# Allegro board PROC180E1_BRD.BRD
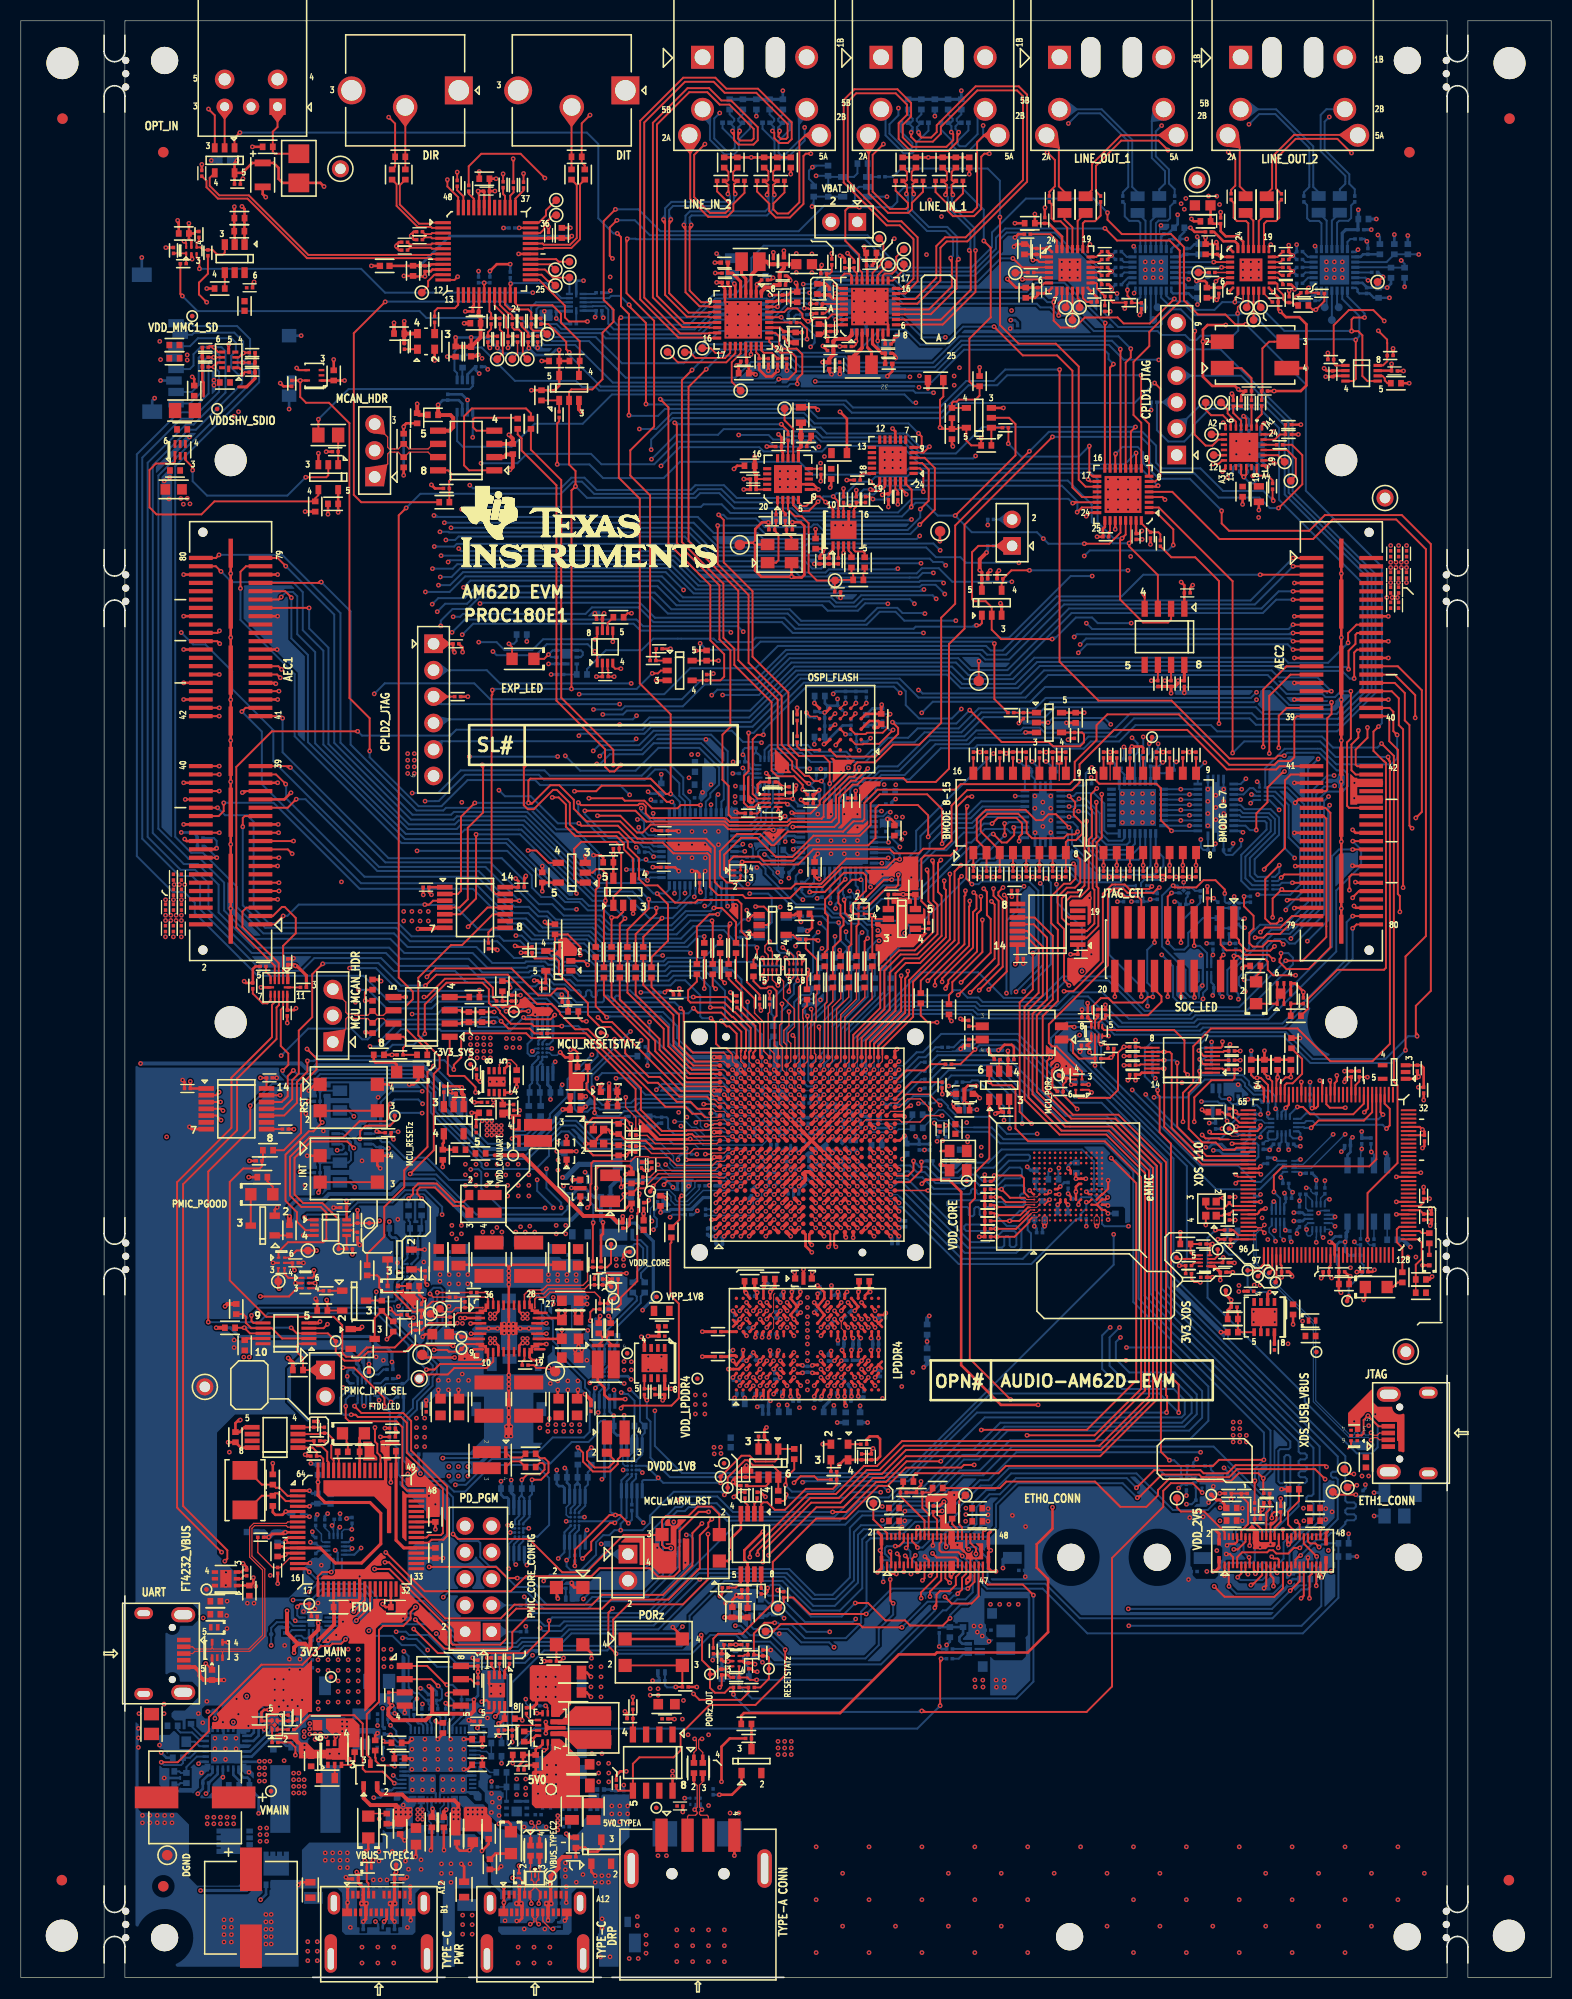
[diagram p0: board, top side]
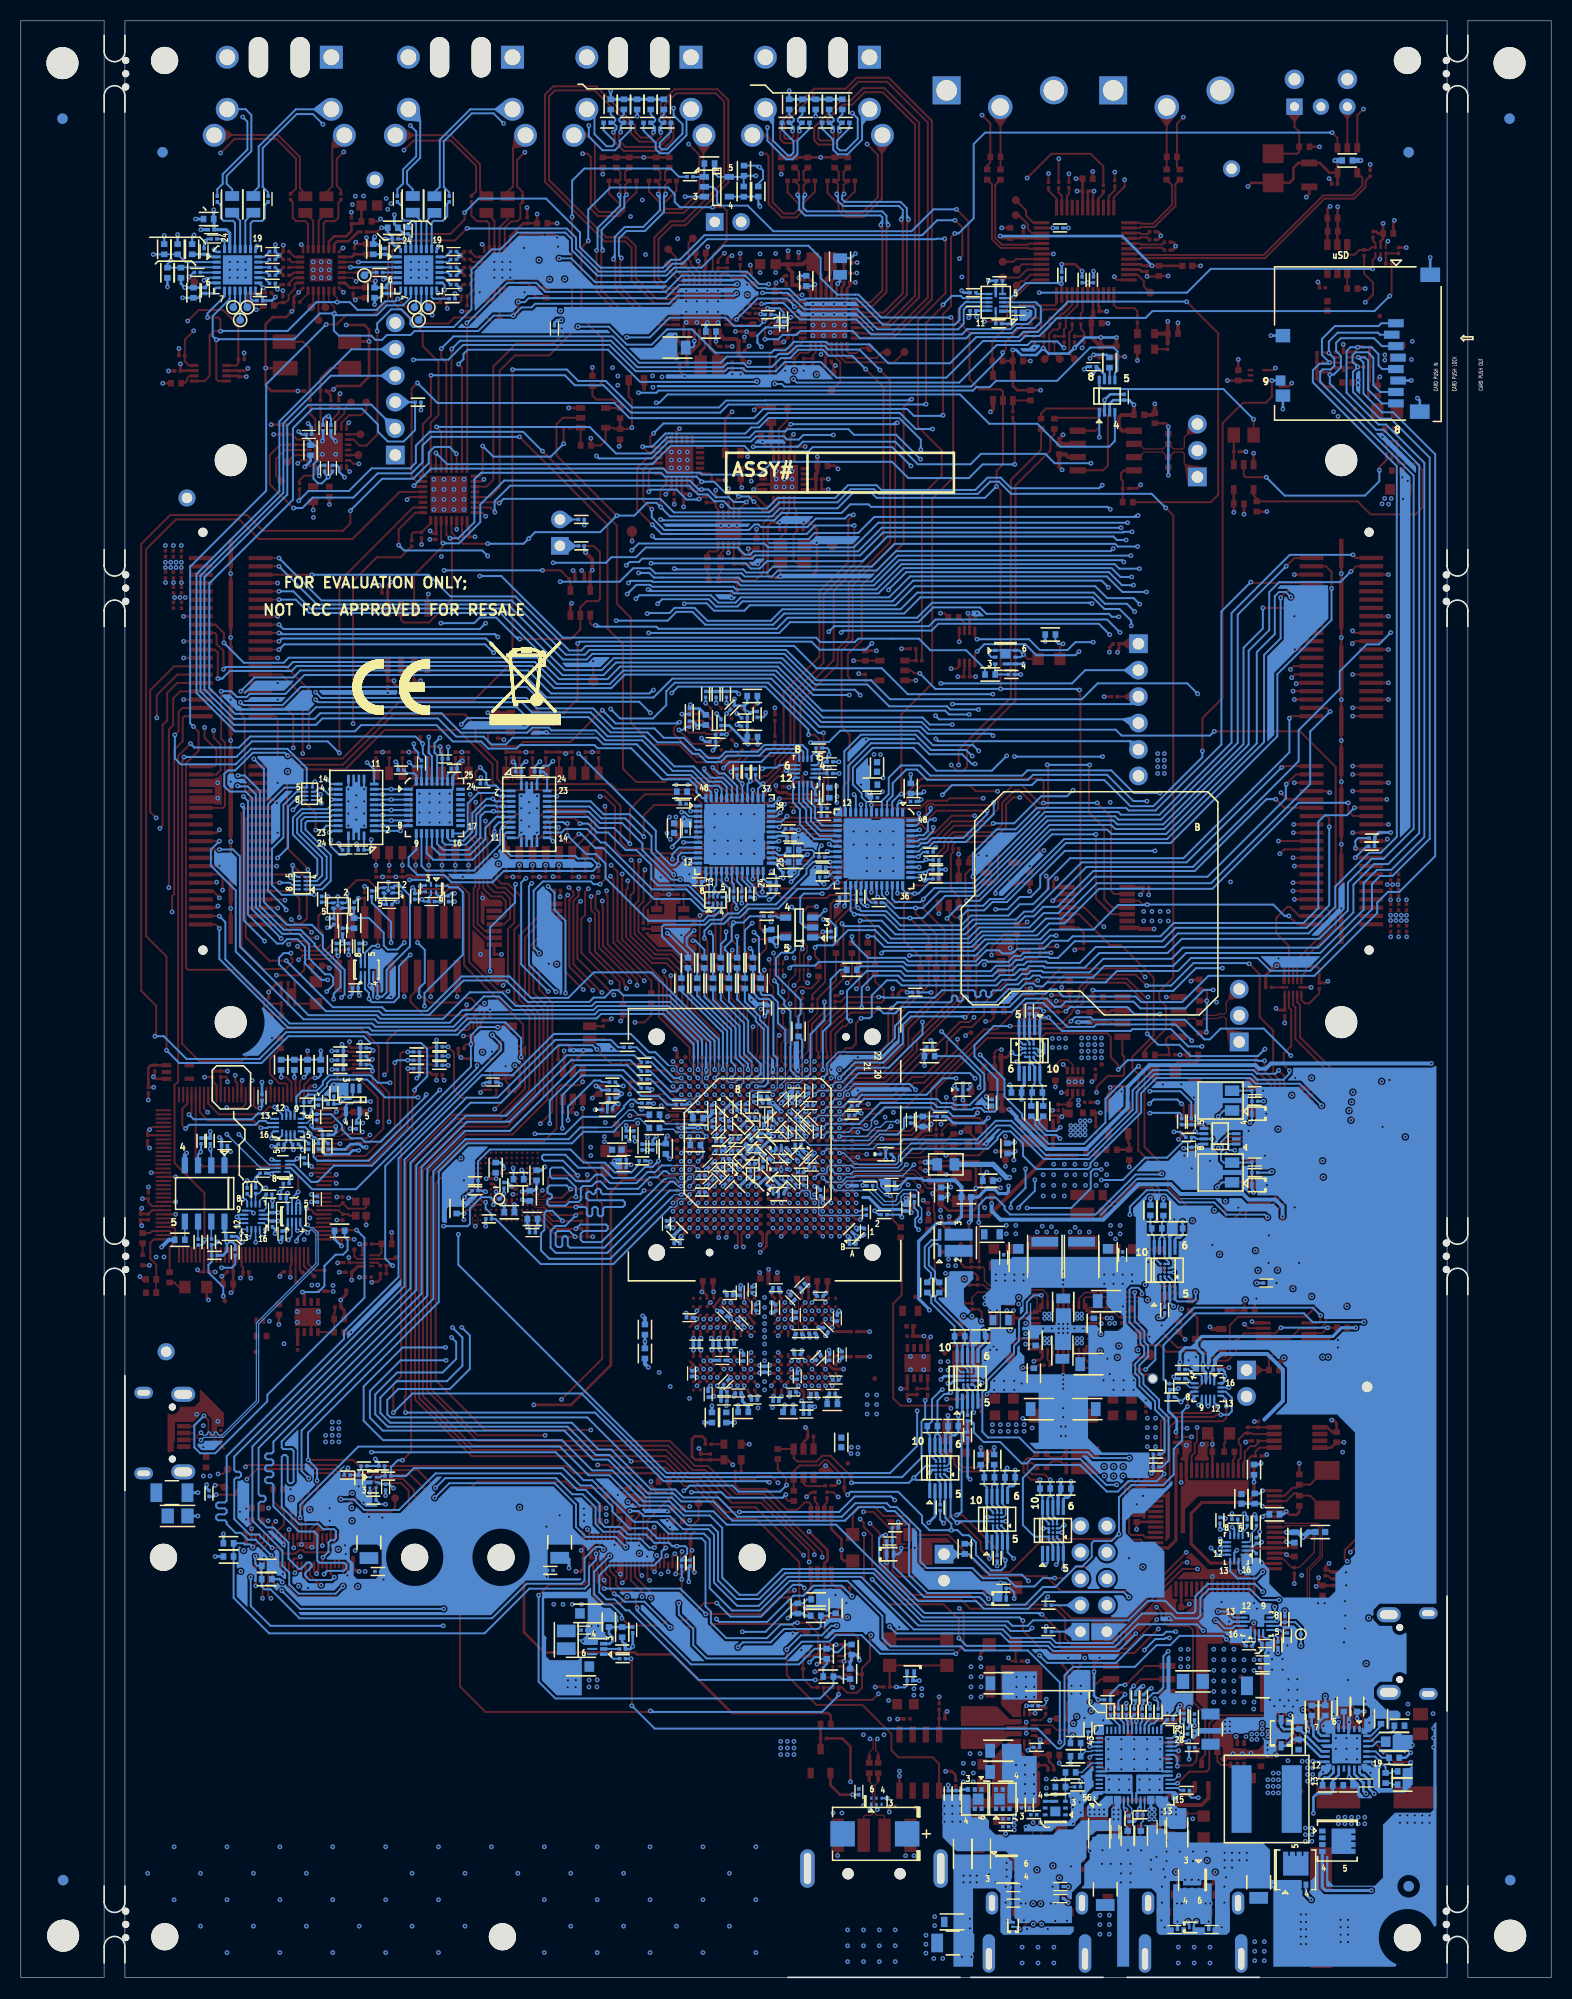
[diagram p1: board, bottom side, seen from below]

Outline 147 x 187.96 mm; copper layers: TOP, L02_GND01, L03_SIG01, L04_PWR1, L05_SIG02, L06_PWR2, L07_GND02, BOTTOM. Coordinates in mm from the lower left corner of the outline.
Outline path: 0,187.96 0,0 8,0 8,187.96 0,187.96 ; 10,187.96 10,0 137,0 137,187.96 10,187.96 ; 139,187.96 147,187.96 147,0 139,0 139,187.96

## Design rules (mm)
net group AUDIO_EXT_REFCLK0: nets AUDIO_EXT_REFCLK0 N27158712
net group AUDIO_EXT_REFCLK1: nets AUDIO_EXT_REFCLK1 AUDIO_EXT_REFCLK1__R
net group CLK_GEN_XI: nets CLK_GEN_XI N27177989
net group CLK_GEN_XO: nets CLK_GEN_XO N27177993
net group CPLD/EXP2_MCASP2_AFSR: nets CPLD/EXP2_MCASP2_AFSR CPLD_MCASP2_AFSR_R
net group CPLD/EXP2_MCASP2_AFSX: nets CPLD/EXP2_MCASP2_AFSX MCASP2_AFSX_R
net group CPLD/EXP2_MCASP2_AXR0: nets CPLD/EXP2_MCASP2_AXR0 MCASP2_AXR0_R
net group CPLD/EXP2_MCASP2_AXR1: nets CPLD/EXP2_MCASP2_AXR1 MCASP2_AXR1_R
net group CPLD/EXP2_MCASP2_AXR3: nets CPLD/EXP2_MCASP2_AXR3 MCASP2_AXR3_R
net group CPLD/EXP2_MCASP2_AXR4: nets CPLD/EXP2_MCASP2_AXR4 MCASP2_AXR4_R
net group CPLD/EXP2_MCASP2_AXR14: nets CPLD/EXP2_MCASP2_AXR14 MCASP2_AXR14_R
net group CPLD/EXP2_MCASP2_AXR15: nets CPLD/EXP2_MCASP2_AXR15 MCASP2_AXR15_R
net group CPLD_CDCE_CLKOUT_1: nets CPLD_CDCE_CLKOUT_1 N27176072
net group CPLD_CDCE_CLKOUT_2: nets CPLD_CDCE_CLKOUT_2 N27175754
net group CPLD_CLOCKIN: nets CPLD_CLOCKIN N27177966
net group CPLD_OBSCLK0: nets CPLD_OBSCLK0 CPLD_OBSCLK0_R
net group CPSW_RGMII1_TD0: nets CPSW_RGMII1_TD0 N27152136
net group CPSW_RGMII1_TD1: nets CPSW_RGMII1_TD1 N27152138
net group CPSW_RGMII1_TD2: nets CPSW_RGMII1_TD2 N27152140
net group CPSW_RGMII1_TD3: nets CPSW_RGMII1_TD3 N27152142
net group CPSW_RGMII1_TXC: nets CPSW_RGMII1_TXC CPSW_RGMII_TXC_R
net group CPSW_RGMII2_TD0: nets CPSW_RGMII2_TD0 N27152150
net group CPSW_RGMII2_TD1: nets CPSW_RGMII2_TD1 N27152152
net group CPSW_RGMII2_TD2: nets CPSW_RGMII2_TD2 N27152154
net group CPSW_RGMII2_TD3: nets CPSW_RGMII2_TD3 N27152156
net group CPSW_RGMII2_TXC: nets CPSW_RGMII2_TXC CPSW_RGMII2_TXC_R
net group DAC_LAT_CTRL: nets DAC_LAT_CTRL N27178331
net group DIX_MCLK: nets DIX_MCLK N26517285
net group DIX_OP_IN: nets DIX_OP_IN_N DIX_OP_IN_P
net group DIX_RX1: nets DIX_RX1_N DIX_RX1_P
net group DIX_RX2: nets DIX_RX2_N DIX_RX2_P
net group DIX_RX3: nets DIX_RX3_N DIX_RX3_P
net group DIX_TX: nets DIX_TX_N DIX_TX_P
net group EXP1_GPIO0_37: nets EXP1_GPIO0_37 EXP1_GPIO0_37_R
net group EXP2_MCASP2_AXR5: nets EXP2_MCASP2_AXR5 EXP2_MCASP2_AXR5_R
net group EXP2_MCASP2_AXR6: nets EXP2_MCASP2_AXR6 EXP2_MCASP2_AXR6_R
net group EXP2_MCASP2_AXR7: nets EXP2_MCASP2_AXR7 EXP2_MCASP2_AXR7_R
net group EXP2_MCASP2_AXR8: nets EXP2_MCASP2_AXR8 EXP2_MCASP2_AXR8_R
net group EXP2_MCASP2_AXR9: nets EXP2_MCASP2_AXR9 EXP2_MCASP2_AXR9_R
net group EXP2_MCASP2_AXR10: nets EXP2_MCASP2_AXR10 EXP2_MCASP2_AXR10_R
net group EXP2_MCASP2_AXR11: nets EXP2_MCASP2_AXR11 EXP2_MCASP2_AXR11_R
net group EXP2_MCASP2_AXR12: nets EXP2_MCASP2_AXR12 EXP2_MCASP2_AXR12_R
net group EXP2_MCASP2_AXR13: nets EXP2_MCASP2_AXR13 EXP2_MCASP2_AXR13_R
net group MCAN0: nets MCAN0_CAN_H MCAN0_CAN_L
net group MCAN1: nets MCAN1_CAN_H MCAN1_CAN_L
net group MMC1_CLK: nets MMC1_CLK MMC1_CLK_R
net group OSPI0_CSN0: nets OSPI0_CSN0 OSPI_CS
net group OSPI_CLK: nets OSPI_CLK SOC_OSPI_CLK
net group OSPI_DQS: nets OSPI_DQS OSPI_DQS_SOC
net group PCM1_IN1: nets PCM1_IN1N PCM1_IN1P
net group PCM1_IN2: nets PCM1_IN2N PCM1_IN2P
net group PCM1_IN3: nets PCM1_IN3N PCM1_IN3P
net group PCM1_IN4: nets PCM1_IN4N PCM1_IN4P
net group PCM2_IN1: nets PCM2_IN1N PCM2_IN1P
net group PCM2_IN2: nets PCM2_IN2N PCM2_IN2P
net group PCM2_IN3: nets PCM2_IN3N PCM2_IN3P
net group PCM2_IN4: nets PCM2_IN4N PCM2_IN4P
net group SEC_REF_N: nets N27175817 SEC_REF_N
net group SEC_REF_P: nets N27175821 SEC_REF_P
net group SOC_MMC0_CLK: nets MMC0_CLK SOC_MMC0_CLK
net group SOC_OSPI_DQ0: nets OSPI_DQ0 SOC_OSPI_DQ0
net group SOC_OSPI_DQ1: nets OSPI_DQ1 SOC_OSPI_DQ1
net group SOC_OSPI_DQ2: nets OSPI_DQ2 SOC_OSPI_DQ2
net group SOC_OSPI_DQ3: nets OSPI_DQ3 SOC_OSPI_DQ3
net group SOC_OSPI_DQ4: nets OSPI_DQ4 SOC_OSPI_DQ4
net group SOC_OSPI_DQ5: nets OSPI_DQ5 SOC_OSPI_DQ5
net group SOC_OSPI_DQ6: nets OSPI_DQ6 SOC_OSPI_DQ6
net group SOC_OSPI_DQ7: nets OSPI_DQ7 SOC_OSPI_DQ7
net group SOC_USB0: nets SOC_USB0_DM SOC_USB0_DP
net group SOC_USB1_DM: nets SOC_USB1_DM USB_TYPEACONN_DM
net group SOC_USB1_DP: nets SOC_USB1_DP USB_TYPEACONN_DP
net group TAD5212_1_DIN: nets TAD5212_1_DIN TAD5212_1_DIN_R
net group TAD5212_2_DIN: nets TAD5212_2_DIN TAD5212_2_DIN_R
net group TAD5212_3_DIN: nets TAD5212_3_DIN TAD5212_3_DIN_R
net group TAD5212_4_DIN: nets TAD5212_4_DIN TAD5212_4_DIN_R
net group TAD5212_MCASP2_ACLKX: nets N26567066 TAD5212_MCASP2_ACLKX
net group USBC_CONN2: nets USBC_CONN2_DM USBC_CONN2_DP
net group WKUP_LFOSCO_XO: nets N21761024 WKUP_LFOSCO_XO
net group XDS_USB: nets XDS_USB_DM XDS_USB_DP
net group EMMC: nets SOC_MMC0_DAT0
net group JTAG: nets N27154979 SOC_TCK SOC_TDI SOC_TDO SOC_TMS SOC_TRST#
net group MCU_SPI0: nets MCU_SPI0_CLK MCU_SPI0_D0 MCU_SPI0_D1
net group MMC0_SD-CARD: nets MMC1_SDCD
net group PWR: nets DIX_3V3_SYS VCC1V1_N VCC1V8_CLKBUF VCC1V8_SYS_N VCC_5V0_FB VCC_CORE_N

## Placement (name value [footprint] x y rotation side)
ACC*  -  [unnamed#4]  75.56 79.99 90 top
C1  0.1uF  [CAP0402_0-75]  23.71 175.85 180 top
C2  0.1uF  [CAP0402_0-75]  73.96 174.35 270 top
C3  0.1uF  [CAP0402_0-75]  91.1 174.35 270 top
C4  0.1uF  [CAP0201_0-5]  17.39 173.31 90 top
C5  0.1uF  [CAP0402_0-75]  52.9 173.19 90 top
C6  0.1uF  [CAP0402_0-75]  54.17 173.19 90 top
C7  0.1uF  [CAP0402_0-75]  35.66 173.19 90 top
C8  0.1uF  [CAP0402_0-75]  36.93 173.19 90 top
C9  10uF  [CAPCT0805H_1]  23.23 173.16 270 top
C10  10uF  [CAP0402_0-75]  44.52 172.79 180 top
C11  2.2uF  [CAP0201_0-75]  67.22 172.59 0 top
C12  2.2uF  [CAP0201_0-75]  69.17 172.59 180 top
C13  2.2uF  [CAP0201_0-75]  71.06 172.59 0 top
C14  2.2uF  [CAP0201_0-75]  73.01 172.59 180 top
C15  2.2uF  [CAP0201_0-75]  84.37 172.59 0 top
C16  2.2uF  [CAP0201_0-75]  86.32 172.59 180 top
C17  2.2uF  [CAP0201_0-75]  88.21 172.59 0 top
C18  2.2uF  [CAP0201_0-75]  90.16 172.59 180 top
C19  0.1uF  [CAP0201_0-5]  44.73 171.6 180 top
C20  1uF  [CAP0201_0-5]  116.26 171.07 270 top
C21  1uF  [CAP0201_0-5]  121.08 171.06 270 top
C22  1uF  [CAP0201_0-5]  98.79 170.85 270 top
C23  1uF  [CAP0201_0-5]  103.72 170.85 270 top
C24  47uF  [CAP0805_1-5]  100.25 170.3 270 top
C25  47uF  [CAP0805_1-5]  102.28 170.3 270 top
C26  47uF  [CAP0805_1-5]  117.65 170.3 270 top
C27  47uF  [CAP0805_1-5]  119.68 170.3 270 top
C28  0.1uF  [CAP0402_0-75]  21 169 180 top
C29  0.1uF  [CAP0201_0-5]  98.36 168.78 90 top
C30  0.1uF  [CAP0201_0-5]  115.25 168.75 90 top
C31  10uF  [CAP0402_0-75]  113.79 168.7 180 top
C32  10uF  [CAP0402_0-75]  96.92 168.51 180 top
C33  4.7uF  [CAP0402_0-75]  20.99 167.75 0 top
C34  0.1uF  [CAP0201_0-5]  38.3 167.7 180 top
C35  1uF  [CAP0201_0-5]  114.07 167.68 180 top
C36  10uF  [CAP0402_0-75]  51.97 167.58 90 top
C37  0.1uF  [CAP0402_0-75]  15.66 167.53 180 top
C38  1uF  [CAP0201_0-5]  96.68 167.46 180 top
C39  0.1uF  [CAP0201_0-5]  50.69 167.36 90 top
C40  0.1uF  [CAP0201_0-5]  38.3 166.93 180 top
C41  0.1uF  [CAP0201_0-5]  36.87 166.7 180 top
C42  10uF  [CAP0402_0-75]  96.4 166.02 90 top
C43  10uF  [CAP0402_0-75]  113.8 166.02 90 top
C44  0.1uF  [CAP0201_0-5]  36.87 165.93 180 top
C45  0.1uF  [CAP0201_0-5]  97.55 165.81 90 top
C46  0.1uF  [CAP0201_0-5]  114.95 165.81 90 top
C47  0.1uF  [CAP0201_0-5]  104.11 165.79 0 top
C48  0.1uF  [CAP0201_0-5]  121.51 165.79 0 top
C49  0.1uF  [CAP0402_0-75]  81.7 165.66 0 top
C50  0.1uF  [CAP0201_0-5]  104.11 165.03 0 top
C51  0.1uF  [CAP0201_0-5]  121.51 165.03 0 top
C52  2.2uF  [CAP0201_0-75]  73.3 164.91 90 top
C53  0.1uF  [CAP0201_0-5]  72.28 164.85 270 top
C54  2.2uF  [CAP0201_0-75]  67.58 164.73 180 top
C55  1uF  [CAP0201_0-5]  81.51 164.48 0 top
C56  0.1uF  [CAP0201_0-5]  104.11 164.27 0 top
C57  0.1uF  [CAP0201_0-5]  121.51 164.27 0 top
C58  0.1uF  [CAP0201_0-5]  38.82 164.15 270 top
C59  10uF  [CAP0402_0-75]  37.68 163.94 270 top
C60  0.1uF  [CAP0201_0-5]  67.64 163.72 0 top
C61  0.1uF  [CAP0201_0-5]  104.11 163.51 0 top
C62  0.1uF  [CAP0201_0-5]  121.51 163.51 0 top
C63  1uF  [CAP0201_0-5]  73.17 163.46 0 top
C64  0.1uF  [CAP0201_0-5]  71.44 163.07 0 top
C65  1uF  [CAP0201_0-5]  67.64 162.83 180 top
C66  1uF  [CAP0201_0-5]  104.11 162.62 0 top
C67  1uF  [CAP0201_0-5]  121.51 162.62 0 top
C68  0.1uF  [CAP0201_0-5]  73.17 162.57 0 top
C69  1uF  [CAP0201_0-5]  21.98 162.31 0 top
C70  220pF  [CAP0402_0-75]  19.1 162.24 180 top
C71  10uF  [CAP0402_0-75]  76.52 162.2 90 top
C72  0.1uF  [CAP0201_0-5]  97.68 162.05 270 top
C73  0.1uF  [CAP0201_0-5]  115.08 162.05 270 top
C74  0.1uF  [CAP0201_0-5]  77.66 161.91 90 top
C75  10uF  [CAP0402_0-75]  96.53 161.84 270 top
C76  10uF  [CAP0402_0-75]  113.92 161.84 270 top
C77  10uF  [CAP0402_0-75]  74.58 161.42 90 top
C78  0.1uF  [CAP0201_0-5]  73.17 161.34 90 top
C79  0.1uF  [CAP0201_0-5]  43.7 160.05 180 top
C80  10uF  [CAP0402_0-75]  43.67 158.9 180 top
C81  0.1uF  [CAP0201_0-5]  77.77 158.4 270 top
C82  10uF  [CAP0402_0-75]  76.66 158.34 270 top
C83  4.7uF  [CAP0402_0-75]  36.34 157.91 180 top
C84  0.1uF  [CAP0201_0-5]  73.28 157.83 270 top
C85  10uF  [CAP0402_0-75]  74.43 157.54 270 top
C86  0.1uF  [CAP0201_0-5]  77.77 157.17 180 top
C87  1uF  [CAP0201_0-5]  83.31 156.91 0 top
C88  2.2uF  [CAP0402_0-75]  14.75 156.81 0 top
C89  0.1uF  [CAP0201_0-5]  79.5 156.67 180 top
C90  1uF  [CAP0201_0-5]  77.77 156.28 180 top
C91  10uF  [CAP0402_0-75]  41.76 156.18 270 top
C92  0.1uF  [CAP0201_0-5]  83.31 156.02 180 top
C93  0.1uF  [CAP0402_0-75]  14.76 155.55 0 top
C94  0.1uF  [CAP0402_0-75]  51.23 155.28 180 top
C95  1uF  [CAP0201_0-5]  69.44 155.26 180 top
C96  2.2uF  [CAP0201_0-75]  83.37 155.01 0 top
C97  0.1uF  [CAP0201_0-5]  78.66 154.89 90 top
C98  2.2uF  [CAP0201_0-75]  77.65 154.83 270 top
C99  0.1uF  [CAP0201_0-5]  131.95 154.32 0 top
C100  0.1uF  [CAP0402_0-75]  69.44 154.12 180 top
C101  0.1uF  [CAP0201_0-5]  126.03 154.05 90 top
C102  0.1uF  [CAP0402_0-75]  30.05 153.89 270 top
C103  0.1uF  [CAP0402_0-75]  19.6 153.22 0 top
C104  12pF  [CAP0201_0-5]  117.94 152.4 0 top
C105  12pF  [CAP0201_0-5]  119.47 152.39 0 top
C106  0.1uF  [CAP0402_0-75]  39.59 150.11 0 top
C107  4700pF  [CAP0402_0-75]  38.07 149.78 90 top
C108  2.2uF  [CAP0402_0-75]  15.49 148.71 0 top
C109  0.1uF  [CAP0402_0-75]  89.44 148.26 270 top
C110  10uF  [CAP0402_0-75]  75.42 148.08 0 top
C111  0.1uF  [CAP0201_0-5]  75.21 147.06 0 top
C112  0.1uF  [CAP0201_0-5]  72.79 147.06 180 top
C113  0.1uF  [CAP0402_0-75]  47.26 146.82 270 top
C114  10uF  [CAP0402_0-75]  70 145.21 180 top
C115  0.1uF  [CAP0402_0-75]  14.81 144.76 180 top
C116  0.1uF  [CAP0201_0-5]  76.86 144.66 270 top
C117  10uF  [CAP0402_0-75]  77.84 144.43 270 top
C118  0.1uF  [CAP0201_0-5]  70.35 143.94 180 top
C119  10uF  [CAP0603_1]  14.68 142.94 180 top
C120  0.1uF  [CAP0201_0-5]  70.35 142.94 180 top
C121  10uF  [CAP0402_0-75]  117.36 142.72 270 top
C122  0.01uF  [CAP0201_0-5]  83.34 142.23 90 top
C123  0.1uF  [CAP0402_0-75]  29.99 141.56 180 top
C124  12pF  [CAP0201_0-5]  72.14 139.07 180 top
C125  12pF  [CAP0201_0-5]  73.83 139.07 180 top
C126  0.01uF  [CAP0201_0-5]  107.13 138.42 90 top
C127  10uF  [CAP0402_0-75]  76.34 137.74 90 top
C128  0.1uF  [CAP0201_0-5]  131.58 136.77 90 top
C129  0.1uF  [CAP0201_0-5]  132.35 136.77 90 top
C130  1uF  [CAP0201_0-5]  133.11 136.77 90 top
C131  0.1uF  [CAP0201_0-5]  76.74 136.07 270 top
C132  0.1uF  [CAP0201_0-5]  77.63 136.07 270 top
C133  0.1uF  [CAP0201_0-5]  131.58 134.71 270 top
C134  1uF  [CAP0201_0-5]  132.34 134.71 270 top
C135  1uF  [CAP0201_0-5]  133.1 134.71 270 top
C136  0.1uF  [CAP0201_0-5]  92.59 134.34 0 top
C137  0.1uF  [CAP0201_0-5]  131.58 133.27 90 top
C138  1uF  [CAP0201_0-5]  132.34 133.27 90 top
C139  0.01uF  [CAP0201_0-5]  78.46 133.1 0 top
C140  0.1uF  [CAP0201_0-5]  112.04 133 0 top
C141  0.1uF  [CAP0201_0-5]  131.58 131.82 270 top
C142  1uF  [CAP0201_0-5]  132.34 131.82 270 top
C143  0.1uF  [CAP0201_0-5]  55.58 130.47 180 top
C144  0.1uF  [CAP0201_0-5]  56.14 124.96 180 top
C145  0.1uF  [CAP0201_0-5]  41.79 128.11 0 top
C146  0.1uF  [CAP0402_0-75]  65.87 126.98 90 top
C147  0.1uF  [CAP0201_0-5]  111.76 124.29 270 top
C148  0.1uF  [CAP0402_0-75]  101.32 121 270 top
C149  4.7uF  [CAP0402_0-75]  82.65 120.89 90 top
C150  0.1uF  [CAP0201_0-5]  72.19 114.83 180 top
C151  0.1uF  [CAP0201_0-5]  73.81 114.09 270 top
C152  0.1uF  [CAP0201_0-5]  79.42 113.01 270 top
C153  0.1uF  [CAP0201_0-5]  80.2 113.01 270 top
C154  0.1uF  [CAP0201_0-5]  75.84 112.77 180 top
C155  10uF  [CAP0402_0-75]  83.91 110.17 90 top
C156  0.1uF  [CAP0201_0-5]  61.82 110.15 0 top
C157  0.1uF  [CAP0402_0-75]  56.43 107.11 180 top
C158  10uF  [CAP0402_0-75]  76.25 106.68 90 top
C159  0.1uF  [CAP0201_0-5]  61.76 106.64 0 top
C160  1uF  [CAP0201_0-5]  14.66 105.69 90 top
C161  0.1uF  [CAP0201_0-5]  15.42 105.69 90 top
C162  0.1uF  [CAP0402_0-75]  50.09 105.66 90 top
C163  0.1uF  [CAP0201_0-5]  65.19 105.44 90 top
C164  0.1uF  [CAP0201_0-5]  38.92 104.73 180 top
C165  0.1uF  [CAP0201_0-5]  48.07 104.73 180 top
C166  0.1uF  [CAP0402_0-75]  85.93 104.51 90 top
C167  1uF  [CAP0201_0-5]  14.66 104.24 270 top
C168  0.1uF  [CAP0201_0-5]  15.42 104.24 270 top
C169  0.1uF  [CAP0201_0-5]  113.98 103.95 90 top
C170  1uF  [CAP0201_0-5]  13.9 102.81 90 top
C171  1uF  [CAP0201_0-5]  14.66 102.81 90 top
C172  0.1uF  [CAP0201_0-5]  15.42 102.81 90 top
C173  0.1uF  [CAP0402_0-75]  75.27 102.17 0 top
C174  1uF  [CAP0201_0-5]  13.89 100.75 270 top
C175  0.1uF  [CAP0201_0-5]  14.65 100.75 270 top
C176  0.1uF  [CAP0201_0-5]  15.42 100.75 270 top
C177  0.1uF  [CAP0201_0-5]  101.81 98.28 0 top
C178  0.1uF  [CAP0201_0-5]  96.01 97.88 0 top
C179  0.1uF  [CAP0201_0-5]  25.64 97.56 90 top
C180  4700pF  [CAP0402_0-75]  33.79 95.37 90 top
C181  0.1uF  [CAP0201_0-5]  50.42 95.27 90 top
C182  100pF  [CAP0201_0-5]  52.29 93.68 180 top
C183  0.1uF  [CAP0201_0-5]  25.59 92.64 270 top
C184  0.1uF  [CAP0402_0-75]  43.04 92.25 90 top
C185  0.1uF  [CAP0402_0-75]  44.31 92.25 90 top
C186  0.1uF  [CAP0201_0-5]  102.21 92.2 0 top
C187  0.1uF  [CAP0201_0-5]  102.15 89.55 0 top
C188  100pF  [CAP0201_0-5]  53.19 88.38 180 top
C189  0.01uF  [CAP0201_0-5]  95.11 88.16 180 top
C190  0.01uF  [CAP0201_0-5]  134.14 87.34 270 top
C191  0.1uF  [CAP0201_0-5]  43.78 86.96 90 top
C192  0.1uF  [CAP0201_0-5]  106.79 86.73 180 top
C193  220pF  [CAP0402_0-75]  47.63 86.66 270 top
C194  0.1uF  [CAP0201_0-5]  23.88 86.41 0 top
C195  0.1uF  [CAP0201_0-5]  16 85.39 180 top
C196  10uF  [EMIFIL_NFM18C_0603_1-4]  56.51 85.07 0 top
C197  1uF  [CAP0201_0-5]  42.08 84.92 180 top
C198  10uF  [EMIFIL_NFM18C_0603_1-4]  90.64 84.88 0 top
C199  1uF  [CAP0201_0-5]  44.54 84.06 0 top
C200  10uF  [CAP0402_1]  56.83 83.7 180 top
C201  10uF  [CAP0402_1]  53.24 83.36 0 top
C202  10uF  [CAP0402_1]  90.64 83.3 0 top
C203  0.1uF  [CAP0201_0-5]  116.07 83.17 270 top
C204  10uF  [CAP0402_0-75]  44.5 83.05 180 top
C205  18pF  [CAP0402_0-75]  57.42 81.5 90 top
C206  1uF  [CAP0201_0-5]  88.3 81.5 90 top
C207  1uF  [CAP0201_0-5]  43.74 81.44 90 top
C208  0.01uF  [CAP0201_0-5]  134.82 80.62 270 top
C209  18pF  [CAP0402_0-75]  57.42 79.46 90 top
C210  10uF  [EMIFIL_NFM18C_0603_1-4]  52.42 79.36 90 top
C211  4.7uF  [CAP0201_0-5]  59.62 78.03 270 top
C212  1uF  [CAP0201_0-5]  60.61 78.03 270 top
C213  18pF  [CAP0402_0-75]  58.66 76.76 270 top
C214  10uF  [EMIFIL_NFM18C_0603_1-4]  53.74 75.82 90 top
C215  0.1uF  [CAP0201_0-5]  134.75 75.08 270 top
C216  18pF  [CAP0402_0-75]  58.66 74.84 90 top
C217  12pF  [CAP0201_0-5]  116.08 74.68 270 top
C218  10uF  [CAP0402_1]  61.45 74.59 90 top
C219  1uF  [CAP0201_0-5]  59.82 74.14 90 top
C220  0.1uF  [CAP0201_0-5]  31.01 73.94 0 top
C221  0.01uF  [CAP0201_0-5]  134.75 73.05 270 top
C222  1uF  [CAP0201_0-5]  135.51 73.05 270 top
C223  12pF  [CAP0201_0-5]  116.08 73.03 90 top
C224  1uF  [CAP0201_0-5]  57.82 72.25 270 top
C225  0.1uF  [CAP0201_0-5]  115.92 70.9 0 top
C226  22uF  [CAP0603_1]  40.14 69.17 270 top
C227  47uF  [CAP0805_1-5]  42.04 69.17 270 top
C228  47uF  [CAP0805_1-5]  51.7 69.17 270 top
C229  22uF  [CAP0603_1]  53.53 69.17 270 top
C230  0.1uF  [CAP0201_0-5]  26.37 68.64 180 top
C231  0.1uF  [CAP0201_0-5]  121.39 67.78 180 top
C232  0.01uF  [CAP0201_0-5]  125.37 67.78 180 top
C233  1uF  [CAP0201_0-5]  126.88 67.78 0 top
C234  0.01uF  [CAP0201_0-5]  129.12 67.78 180 top
C235  0.1uF  [CAP0201_0-5]  115.49 67.74 180 top
C236  0.1uF  [CAP0201_0-5]  113.63 67.25 180 top
C237  10uF  [CAP0402_0-75]  71.94 67.08 180 top
C238  10uF  [CAP0402_0-75]  70.01 66.87 180 top
C239  10uF  [CAP0402_0-75]  81 66.87 0 top
C240  2.2uF  [CAP0402_0-75]  127.09 66.61 0 top
C241  1uF  [CAP0201_0-5]  118.15 65.91 180 top
C242  2.2uF  [CAP0603_1]  52.77 65 0 top
C243  15pF  [CAP0201_0-5]  116.55 64.39 0 top
C244  2.2uF  [CAP0402_0-75]  122.21 64.17 270 top
C245  100pF  [CAP0201_0-5]  38.47 63.16 270 top
C246  2.2uF  [CAP0603_1]  52.77 63.15 0 top
C247  2.2uF  [CAP0201_0-75]  61.58 62.54 0 top
C248  100pF  [CAP0201_0-5]  37.92 62.44 90 top
C249  2.2uF  [CAP0603_1]  40.34 61.79 180 top
C250  4.7uF  [CAP0402_0-75]  123.89 61.61 180 top
C251  0.1uF  [CAP0201_0-5]  61.58 61.6 0 top
C252  2.2uF  [CAP0603_1]  52.77 61.34 0 top
C253  0.1uF  [CAP0402_0-75]  21.5 60.72 90 top
C254  2.2uF  [CAP0603_1]  52.77 59.54 0 top
C255  1uF  [CAP0201_0-5]  61.84 56.26 270 top
C256  2.2uF  [CAP0603_1]  40.31 54.79 90 top
C257  22uF  [CAP0603_1]  42.09 54.79 90 top
C258  22uF  [CAP0603_1]  51.65 54.79 90 top
C259  2.2uF  [CAP0603_1]  53.43 54.79 90 top
C260  0.1uF  [CAP0201_0-5]  54.77 54.66 90 top
C261  0.1uF  [CAP0201_0-5]  38.93 54.61 90 top
C262  0.1uF  [CAP0402_0-75]  20.62 51.89 270 top
C263  4.7uF  [CAP0402_0-75]  35.53 50.55 180 top
C264  0.1uF  [CAP0402_0-75]  33.03 50.49 180 top
C265  1uF  [CAP0201_0-5]  81.7 50 90 top
C266  0.1uF  [CAP0201_0-5]  80.76 50 270 top
C267  0.1uF  [CAP0402_0-75]  129.2 49.48 270 top
C268  0.01uF  [CAP0201_0-5]  69.61 48.33 270 top
C269  18pF  [CAP0402_0-75]  24.2 47.82 90 top
C270  18pF  [CAP0402_0-75]  24.2 45.78 270 top
C271  10uF  [CAP0402_0-75]  124.31 45.09 0 top
C272  10uF  [CAP0402_0-75]  83.88 45.09 0 top
C273  10uF  [CAP0402_0-75]  116.31 45.09 0 top
C274  10uF  [CAP0402_0-75]  91.86 45.06 0 top
C275  0.1uF  [CAP0402_0-75]  39.82 44.24 270 top
C276  0.1uF  [CAP0402_0-75]  116.31 43.88 0 top
C277  0.1uF  [CAP0402_0-75]  124.32 43.87 0 top
C278  0.1uF  [CAP0402_0-75]  83.88 43.84 0 top
C279  0.1uF  [CAP0402_0-75]  91.88 43.8 0 top
C280  0.1uF  [CAP0402_0-75]  24.66 40.92 90 top
C281  0.1uF  [CAP0402_0-75]  39.82 40.76 90 top
C282  0.1uF  [CAP0201_0-5]  24.67 39.09 90 top
C283  0.01uF  [CAP0201_0-5]  21.71 38.86 270 top
C284  0.1uF  [CAP0201_0-5]  69.53 37.24 0 top
C285  2.2uF  [CAP0402_0-75]  21.95 37.15 270 top
C286  1uF  [CAP0201_0-5]  69.53 36.48 0 top
C287  10uF  [CAP0402_0-75]  18.69 36.13 180 top
C288  0.1uF  [CAP0402_0-75]  30.53 35.57 180 top
C289  0.1uF  [CAP0402_0-75]  36.03 35.57 180 top
C290  10uF  [CAP0402_0-75]  68.35 35.07 90 top
C291  0.1uF  [CAP0402_0-75]  18.69 34.89 180 top
C292  0.1uF  [CAP0201_0-5]  43.91 30.19 90 top
C293  0.1uF  [CAP0201_0-5]  69.9 29.92 270 top
C294  10uF  [CAP0805_1-5]  53.06 29.27 0 top
C295  0.1uF  [CAP0402_0-75]  18.37 29.05 270 top
C296  10uF  [CAP0603_1]  53.06 27.36 0 top
C297  10uF  [CAP0603_1]  62.02 26.24 0 top
C298  0.1uF  [CAP0402_0-75]  46.97 24.85 0 top
C299  0.1uF  [CAP0201_0-5]  61.88 24.83 0 top
C300  0.01uF  [CAP0201_0-5]  22.84 24.64 0 top
C301  0.01uF  [CAP0201_0-5]  43.85 24.6 180 top
C302  10uF  [CAP0603_1]  29.29 24.21 0 top
C303  4.7uF  [CAP0402_0-75]  40.54 23.95 270 top
C304  0.1uF  [CAP0402_0-75]  48.36 23.13 270 top
C305  220pF  [CAP0402_0-75]  43.84 22.88 180 top
C306  220pF  [CAP0402_0-75]  36.1 22.53 0 top
C307  220pF  [CAP0402_0-75]  34.04 22.28 90 top
C308  330pF  [CAP0402_0-75]  32.06 22.12 90 top
C309  4.7uF  [CAP0402_0-75]  36.37 21.03 0 top
C310  1uF  [CAP0402_0-75]  27.89 20.76 90 top
C311  10uF  [CAP0603_1]  53.84 20.46 0 top
C312  220pF  [CAP0402_0-75]  43.84 20.42 180 top
C313  120pF  [CAP0201_0-5]  48.05 19.92 180 top
C314  22uF  [CAP0805_1-5]  53.86 18.43 0 top
C315  100uF  [CAPAE_FCASE_10-5]  16.74 17.29 180 top
C316  0.1uF  [CAP0201_0-5]  63.32 16.46 0 top
C317  47uF  [CAP0805_1-5]  52.93 15.92 270 top
C318  47uF  [CAP0805_1-5]  55.01 15.91 270 top
C319  10uF  [CAP0402_0-75]  39.48 14.9 90 top
C320  10uF  [CAP0402_0-75]  40.63 14.9 90 top
C321  0.1uF  [CAP0402_0-75]  36.43 14.26 270 top
C322  10uF  [CAP0603_1]  43.42 13.78 270 top
C323  0.1uF  [CAP0402_0-75]  44.94 13.78 270 top
C324  10uF  [CAP0603_1]  37.96 13.54 270 top
C325  0.1uF  [CAP0402_0-75]  41.89 13.43 270 top
C326  0.01uF  [CAP0201_0-5]  36.17 9.46 0 top
C327  0.01uF  [CAP0201_0-5]  32.14 9.45 180 top
C328  100uF  [CAPAE_FCASE_10-5]  22.11 6.68 270 top
C329  0.1uF  [CAP0402_0-75]  87.8 179.93 270 bottom
C330  0.1uF  [CAP0402_0-75]  70.65 179.93 270 bottom
C331  2.2uF  [CAP0201_0-75]  90.68 178.17 180 bottom
C332  2.2uF  [CAP0201_0-75]  88.73 178.17 0 bottom
C333  2.2uF  [CAP0201_0-75]  86.84 178.17 180 bottom
C334  2.2uF  [CAP0201_0-75]  84.89 178.17 0 bottom
C335  2.2uF  [CAP0201_0-75]  73.54 178.17 180 bottom
C336  2.2uF  [CAP0201_0-75]  71.59 178.17 0 bottom
C337  2.2uF  [CAP0201_0-75]  69.7 178.17 180 bottom
C338  2.2uF  [CAP0201_0-75]  67.75 178.17 0 bottom
C339  0.1uF  [CAP0402_0-75]  19.59 174.54 180 bottom
C340  0.1uF  [CAP0402_0-75]  77.54 173.56 90 bottom
C341  1uF  [CAP0201_0-5]  128.13 170.85 270 bottom
C342  1uF  [CAP0201_0-5]  123.25 170.85 270 bottom
C343  1uF  [CAP0201_0-5]  110.83 170.85 270 bottom
C344  1uF  [CAP0201_0-5]  105.85 170.85 270 bottom
C345  47uF  [CAP0805_1-5]  126.7 170.33 270 bottom
C346  47uF  [CAP0805_1-5]  124.67 170.33 270 bottom
C347  47uF  [CAP0805_1-5]  109.35 170.33 270 bottom
C348  47uF  [CAP0805_1-5]  107.27 170.3 270 bottom
C349  10uF  [CAP0402_0-75]  128.96 168.92 0 bottom
C350  10uF  [CAP0402_0-75]  111.27 168.08 0 bottom
C351  0.1uF  [CAP0201_0-5]  128.72 167.89 0 bottom
C352  0.1uF  [CAP0201_0-5]  109.79 167.76 90 bottom
C353  1uF  [CAP0201_0-5]  128.44 167 0 bottom
C354  1uF  [CAP0201_0-5]  111.04 167 0 bottom
C355  10uF  [CAP0402_0-75]  130.55 166.02 90 bottom
C356  10uF  [CAP0402_0-75]  113.15 166.02 90 bottom
C357  0.1uF  [CAP0201_0-5]  129.39 165.81 90 bottom
C358  0.1uF  [CAP0201_0-5]  112 165.81 90 bottom
C359  0.1uF  [CAP0201_0-5]  122.83 165.79 180 bottom
C360  0.1uF  [CAP0201_0-5]  105.43 165.79 180 bottom
C361  0.1uF  [CAP0201_0-5]  122.83 165.03 180 bottom
C362  0.1uF  [CAP0201_0-5]  105.43 165.03 180 bottom
C363  1uF  [CAP0805_1-5]  68.31 164.36 90 bottom
C364  0.1uF  [CAP0201_0-5]  122.83 164.27 180 bottom
C365  0.1uF  [CAP0201_0-5]  105.43 164.27 180 bottom
C366  0.1uF  [CAP0201_0-5]  122.83 163.51 180 bottom
C367  0.1uF  [CAP0201_0-5]  105.43 163.51 180 bottom
C368  10uF  [CAP0402_0-75]  71.56 162.98 90 bottom
C369  1uF  [CAP0201_0-5]  122.83 162.74 180 bottom
C370  1uF  [CAP0201_0-5]  105.43 162.62 180 bottom
C371  0.1uF  [CAP0201_0-5]  129.27 162.05 270 bottom
C372  0.1uF  [CAP0201_0-5]  111.87 162.05 270 bottom
C373  10uF  [CAP0402_0-75]  130.42 161.84 270 bottom
C374  10uF  [CAP0402_0-75]  113.02 161.84 270 bottom
C375  0.1uF  [CAP0201_0-5]  55.53 160.11 0 bottom
C376  0.1uF  [CAP0201_0-5]  51.15 160.06 180 bottom
C377  0.1uF  [CAP0201_0-5]  95.75 158.4 270 bottom
C378  10uF  [CAP0402_0-75]  80.72 158.11 0 bottom
C379  1uF  [CAP0805_1-5]  83.93 156.57 0 bottom
C380  0.1uF  [CAP0201_0-5]  43.98 154.73 0 bottom
C381  0.1uF  [CAP0201_0-5]  41.01 151.8 90 bottom
C382  0.1uF  [CAP0201_0-5]  117.97 148.85 270 bottom
C383  0.1uF  [CAP0201_0-5]  117.21 148.85 270 bottom
C384  0.1uF  [CAP0201_0-5]  119.33 148.22 180 bottom
C385  10uF  [CAP0402_0-75]  119.17 146.71 270 bottom
C386  0.1uF  [CAP0201_0-5]  117.83 144.97 90 bottom
C387  0.1uF  [CAP0201_0-5]  117.07 144.97 90 bottom
C388  0.1uF  [CAP0402_0-75]  76.74 123.09 180 bottom
C389  0.1uF  [CAP0402_0-75]  81.2 120.8 270 bottom
C390  0.1uF  [CAP0402_0-75]  76.73 119.16 180 bottom
C391  0.1uF  [CAP0201_0-5]  106.23 117.05 0 bottom
C392  0.1uF  [CAP0201_0-5]  69.27 116.77 0 bottom
C393  0.1uF  [CAP0201_0-5]  108.51 116.62 270 bottom
C394  0.1uF  [CAP0201_0-5]  99.2 115.82 180 bottom
C395  0.1uF  [CAP0201_0-5]  97.36 115.82 0 bottom
C396  0.1uF  [CAP0201_0-5]  69.29 115.65 0 bottom
C397  10uF  [CAP0402_0-75]  65.21 114.58 0 bottom
C398  10uF  [CAP0402_0-75]  61.52 114.21 90 bottom
C399  10uF  [CAP0402_0-75]  83.49 113.91 0 bottom
C400  10uF  [CAP0402_0-75]  69.34 113.8 90 bottom
C401  0.1uF  [CAP0201_0-5]  65 113.32 0 bottom
C402  0.1uF  [CAP0201_0-5]  61.26 112.96 180 bottom
C403  0.1uF  [CAP0201_0-5]  83.37 112.72 0 bottom
C404  0.1uF  [CAP0201_0-5]  69.83 112.31 0 bottom
C405  0.1uF  [CAP0201_0-5]  69.83 111.54 0 bottom
C406  0.1uF  [CAP0201_0-5]  83.09 110.37 90 bottom
C407  0.1uF  [CAP0201_0-5]  73.13 109.54 180 bottom
C408  0.1uF  [CAP0201_0-5]  115.81 108.3 0 bottom
C409  0.1uF  [CAP0201_0-5]  114.31 108.3 180 bottom
C410  0.1uF  [CAP0201_0-5]  69.97 106.65 0 bottom
C411  0.1uF  [CAP0201_0-5]  73.52 106.14 180 bottom
C412  0.1uF  [CAP0201_0-5]  81.89 105.25 0 bottom
C413  0.1uF  [CAP0201_0-5]  68.07 103.76 0 bottom
C414  0.1uF  [CAP0201_0-5]  107.55 103.35 0 bottom
C415  0.01uF  [CAP0201_0-5]  111.63 103.08 0 bottom
C416  0.01uF  [CAP0201_0-5]  116.94 101.44 90 bottom
C417  8.2pF  [CAP0201_0-5]  116.08 100.51 270 bottom
C418  0.1uF  [CAP0402_0-75]  74.9 100.16 90 bottom
C419  0.1uF  [CAP0201_0-5]  114.51 99.04 270 bottom
C420  0.1uF  [CAP0201_0-5]  114.87 95.06 180 bottom
C421  0.1uF  [CAP0201_0-5]  101.66 86.01 180 bottom
C422  1.0uF  [EMIFIL_NFM15CC_0402_0-5]  56.51 85.28 180 bottom
C423  1uF  [CAP0201_0-5]  90.18 85.23 0 bottom
C424  0.1uF  [CAP0201_0-5]  71.31 85.19 270 bottom
C425  0.1uF  [CAP0201_0-5]  28.47 85.18 0 bottom
C426  0.1uF  [CAP0201_0-5]  72.66 85.05 0 bottom
C427  0.1uF  [CAP0402_0-75]  51.36 85.01 180 bottom
C428  0.1uF  [CAP0402_0-75]  49.36 85.01 0 bottom
C429  0.1uF  [CAP0201_0-5]  75.6 84.65 0 bottom
C430  0.1uF  [CAP0201_0-5]  123.84 84.53 270 bottom
C431  1uF  [CAP0201_0-5]  90.18 84.47 0 bottom
C432  1uF  [CAP0201_0-5]  76.61 84.39 90 bottom
C433  1uF  [CAP0201_0-5]  71.96 84.39 135 bottom
C434  1uF  [CAP0201_0-5]  73.62 84.35 135 bottom
C435  1uF  [CAP0201_0-5]  72.9 84.26 90 bottom
C436  1uF  [CAP0201_0-5]  53.69 84.04 270 bottom
C437  0.1uF  [CAP0201_0-5]  75.45 83.99 0 bottom
C438  0.1uF  [CAP0201_0-5]  71.16 83.74 180 bottom
C439  0.1uF  [CAP0201_0-5]  78.21 83.59 270 bottom
C440  0.1uF  [CAP0201_0-5]  77.41 83.59 90 bottom
C441  0.1uF  [CAP0201_0-5]  80.64 83.5 90 bottom
C442  1.0uF  [EMIFIL_NFM15CC_0402_0-5]  90.66 83.35 180 bottom
C443  1uF  [CAP0201_0-5]  71.86 82.89 315 bottom
C444  1uF  [CAP0201_0-5]  75.16 82.87 270 bottom
C445  1uF  [CAP0201_0-5]  72.79 82.77 225 bottom
C446  1uF  [CAP0201_0-5]  79.81 82.74 90 bottom
C447  0.1uF  [CAP0201_0-5]  76.76 82.64 0 bottom
C448  10uF  [CAP0402_1]  81.95 82.52 0 bottom
C449  22pF  [CAP0201_0-5]  61.55 82.34 90 bottom
C450  0.1uF  [CAP0201_0-5]  75.63 82.31 90 bottom
C451  0.1uF  [CAP0201_0-5]  80.61 81.99 90 bottom
C452  1uF  [CAP0201_0-5]  79.01 81.99 90 bottom
C453  0.1uF  [CAP0201_0-5]  71.16 81.99 225 bottom
C454  1uF  [CAP0201_0-5]  71.91 81.94 45 bottom
C455  0.1uF  [CAP0201_0-5]  114.77 81.79 90 bottom
C456  0.1uF  [CAP0201_0-5]  73.61 81.24 225 bottom
C457  1uF  [CAP0201_0-5]  70.5 81.22 90 bottom
C458  0.1uF  [CAP0201_0-5]  79.96 81.19 315 bottom
C459  0.1uF  [CAP0201_0-5]  76.76 81.19 315 bottom
C460  0.1uF  [CAP0201_0-5]  72.9 81.19 270 bottom
C461  0.1uF  [CAP0201_0-5]  71.96 81.19 225 bottom
C462  0.1uF  [CAP0201_0-5]  75.53 81.07 180 bottom
C463  4.7uF  [CAP0201_0-5]  88.85 81.04 90 bottom
C464  4.7uF  [CAP0201_0-5]  88.09 81.04 90 bottom
C465  0.1uF  [CAP0201_0-5]  74.36 80.79 0 bottom
C466  1uF  [CAP0201_0-5]  78.36 80.54 0 bottom
C467  0.1uF  [CAP0201_0-5]  79.96 80.29 0 bottom
C468  2.2uF  [CAP0201_0-75]  77.08 80.21 135 bottom
C469  0.1uF  [CAP0201_0-5]  121.99 80.04 180 bottom
C470  0.1uF  [CAP0201_0-5]  120.61 80.04 0 bottom
C471  0.1uF  [CAP0201_0-5]  72.32 80.01 0 bottom
C472  0.1uF  [CAP0201_0-5]  79.09 79.93 135 bottom
C473  0.1uF  [CAP0201_0-5]  127.44 79.9 0 bottom
C474  4.7uF  [CAP0201_0-5]  87.33 79.76 90 bottom
C475  1uF  [CAP0201_0-5]  86.29 79.76 90 bottom
C476  10uF  [CAP0402_1]  52.22 79.64 270 bottom
C477  1uF  [CAP0201_0-5]  76.56 79.59 180 bottom
C478  0.1uF  [CAP0201_0-5]  34.53 79.46 90 bottom
C479  0.1uF  [CAP0201_0-5]  79.96 79.44 0 bottom
C480  0.1uF  [CAP0201_0-5]  78.36 79.44 180 bottom
C481  1.0uF  [EMIFIL_NFM15CC_0402_0-5]  63.92 79.08 180 bottom
C482  1.0uF  [EMIFIL_NFM15CC_0402_0-5]  72.11 78.94 315 bottom
C483  1uF  [CAP0201_0-5]  75.32 78.86 45 bottom
C484  1uF  [CAP0201_0-5]  71.14 78.77 135 bottom
C485  0.1uF  [CAP0201_0-5]  73.51 78.74 45 bottom
C486  0.1uF  [CAP0201_0-5]  79.26 78.65 180 bottom
C487  1uF  [CAP0201_0-5]  89.12 78.57 0 bottom
C488  1uF  [CAP0201_0-5]  119.76 78.46 90 bottom
C489  0.1uF  [CAP0201_0-5]  28.47 78.32 0 bottom
C490  0.1uF  [CAP0201_0-5]  76.76 78.14 0 bottom
C491  0.1uF  [CAP0201_0-5]  75.7 78.12 90 bottom
C492  1uF  [CAP0201_0-5]  80.77 78 315 bottom
C493  1uF  [CAP0201_0-5]  78.29 77.93 45 bottom
C494  0.1uF  [CAP0201_0-5]  79.01 77.86 90 bottom
C495  0.1uF  [CAP0201_0-5]  79.86 77.84 0 bottom
C496  0.1uF  [CAP0201_0-5]  71.03 77.84 0 bottom
C497  4.7uF  [CAP0201_0-5]  89.12 77.81 0 bottom
C498  0.1uF  [CAP0402_0-75]  101.39 77.78 90 bottom
C499  0.1uF  [CAP0201_0-5]  72.09 77.34 180 bottom
C500  0.1uF  [CAP0201_0-5]  123.74 77.25 180 bottom
C501  0.1uF  [CAP0201_0-5]  76.91 77.19 270 bottom
C502  0.1uF  [CAP0201_0-5]  79.92 77.13 45 bottom
C503  0.1uF  [CAP0402_0-75]  97.46 77.05 90 bottom
C504  2.2uF  [CAP0402_0-75]  99.18 76.67 0 bottom
C505  10uF  [CAP0402_1]  54.1 76.52 0 bottom
C506  0.1uF  [CAP0201_0-5]  80.76 76.39 315 bottom
C507  1uF  [CAP0201_0-5]  79.16 76.39 315 bottom
C508  0.1uF  [CAP0201_0-5]  72.76 76.39 225 bottom
C509  1uF  [CAP0201_0-5]  71.81 76.39 270 bottom
C510  1uF  [CAP0201_0-5]  63.36 76.38 0 bottom
C511  0.1uF  [CAP0201_0-5]  121.5 76.27 180 bottom
C512  0.1uF  [CAP0201_0-5]  63.36 75.69 0 bottom
C513  1uF  [CAP0201_0-5]  70.19 75.35 270 bottom
C514  0.1uF  [CAP0402_0-75]  98.12 75.08 270 bottom
C515  0.1uF  [CAP0201_0-5]  121.78 74.84 180 bottom
C516  0.1uF  [CAP0201_0-5]  118.51 74.76 270 bottom
C517  0.1uF  [CAP0201_0-5]  61.99 73.91 90 bottom
C518  2.2uF  [CAP0402_0-75]  105.14 73.87 90 bottom
C519  0.1uF  [CAP0201_0-5]  122.82 73.74 270 bottom
C520  0.1uF  [CAP0402_0-75]  100.08 73.5 0 bottom
C521  0.1uF  [CAP0402_0-75]  97.86 72.86 180 bottom
C522  0.1uF  [CAP0201_0-5]  84.99 72.39 90 bottom
C523  0.1uF  [CAP0201_0-5]  122.82 72.37 90 bottom
C524  0.1uF  [CAP0402_0-75]  37.88 71.95 180 bottom
C525  0.1uF  [CAP0402_0-75]  35.89 71.95 0 bottom
C526  0.1uF  [CAP0201_0-5]  65.97 71.64 270 bottom
C527  1uF  [CAP0201_0-5]  97.86 71.54 180 bottom
C528  0.1uF  [CAP0201_0-5]  121.91 71.41 90 bottom
C529  0.1uF  [CAP0201_0-5]  127.04 71.17 0 bottom
C530  0.1uF  [CAP0201_0-5]  83.96 70.49 0 bottom
C531  0.1uF  [CAP0201_0-5]  67.11 70.44 180 bottom
C532  0.1uF  [CAP0201_0-5]  41.16 69.4 270 bottom
C533  100uF  [CAP1210_2-75]  48.64 69.26 270 bottom
C534  100uF  [CAP1210_2-75]  45.11 69.26 270 bottom
C535  2.2uF  [CAP0603_1]  51.18 69.18 270 bottom
C536  2.2uF  [CAP0603_1]  42.57 69.18 270 bottom
C537  0.1uF  [CAP0201_0-5]  52.59 69.13 270 bottom
C538  0.1uF  [CAP0201_0-5]  27.34 66.7 180 bottom
C539  0.1uF  [CAP0201_0-5]  71.95 66.47 135 bottom
C540  1000pF  [CAP0201_0-5]  74.47 66.25 180 bottom
C541  0.01uF  [CAP0201_0-5]  76.75 66.06 270 bottom
C542  0.1uF  [CAP0201_0-5]  77.9 65.79 270 bottom
C543  0.01uF  [CAP0201_0-5]  78.91 65.49 0 bottom
C544  1000pF  [CAP0201_0-5]  70.22 65.44 180 bottom
C545  0.01uF  [CAP0201_0-5]  72.84 65.3 45 bottom
C546  10uF  [CAP0805_1-5]  42.76 64.96 180 bottom
C547  10uF  [CAP0805_1-5]  46.87 64.41 270 bottom
C548  0.1uF  [CAP0201_0-5]  76.4 64.35 90 bottom
C549  0.1uF  [CAP0201_0-5]  74.49 64.33 90 bottom
C550  0.1uF  [CAP0201_0-5]  79.4 63.69 45 bottom
C551  0.1uF  [CAP0201_0-5]  72.51 63.63 90 bottom
C552  0.1uF  [CAP0201_0-5]  82.78 63.37 0 bottom
C553  0.1uF  [CAP0201_0-5]  68.57 63.31 90 bottom
C554  0.1uF  [CAP0201_0-5]  77.84 62.83 225 bottom
C555  0.47uF  [CAP0402_0-75]  43.93 62.82 270 bottom
C556  0.1uF  [CAP0201_0-5]  69.68 62.2 45 bottom
C557  0.1uF  [CAP0201_0-5]  70.99 61.86 0 bottom
C558  0.1uF  [CAP0201_0-5]  72.26 61.83 0 bottom
C559  0.1uF  [CAP0402_0-75]  56.81 61.57 180 bottom
C560  0.1uF  [CAP0402_0-75]  54.82 61.57 0 bottom
C561  4.7uF  [CAP0402_0-75]  49.53 61.2 90 bottom
C562  0.1uF  [CAP0201_0-5]  78.78 60.86 180 bottom
C563  0.1uF  [CAP0201_0-5]  82.11 60.82 0 bottom
C564  0.1uF  [CAP0201_0-5]  80.22 60.82 180 bottom
C565  10uF  [CAP0805_1-5]  46.95 60.21 90 bottom
C566  0.1uF  [CAP0201_0-5]  72.4 59.84 0 bottom
C567  0.1uF  [CAP0201_0-5]  68.1 59.83 90 bottom
C568  0.1uF  [CAP0201_0-5]  69.31 59.56 270 bottom
C569  0.1uF  [CAP0201_0-5]  77.57 59.49 270 bottom
C570  1000pF  [CAP0201_0-5]  70.37 59.49 315 bottom
C571  1000pF  [CAP0201_0-5]  79.62 59.27 0 bottom
C572  10uF  [CAP0805_1-5]  44.44 58.91 180 bottom
C573  0.1uF  [CAP0201_0-5]  75.56 58.42 90 bottom
C574  0.1uF  [CAP0201_0-5]  33.72 58.37 180 bottom
C575  0.1uF  [CAP0201_0-5]  32.2 58.37 0 bottom
C576  0.47uF  [CAP0402_0-75]  49.69 58.03 270 bottom
C577  0.1uF  [CAP0201_0-5]  82.57 58 270 bottom
C578  0.1uF  [CAP0201_0-5]  72.42 57.73 270 bottom
C579  0.1uF  [CAP0201_0-5]  68.73 57.38 180 bottom
C580  0.1uF  [CAP0201_0-5]  79.28 57.17 315 bottom
C581  1000pF  [CAP0201_0-5]  79.46 56.25 0 bottom
C582  0.1uF  [CAP0201_0-5]  72.82 56.22 180 bottom
C583  1000pF  [CAP0201_0-5]  78.08 56.14 0 bottom
C584  0.01uF  [CAP0201_0-5]  69.05 56.1 0 bottom
C585  0.1uF  [CAP0201_0-5]  70.84 56.09 0 bottom
C586  0.1uF  [CAP0201_0-5]  80.98 56.02 90 bottom
C587  0.01uF  [CAP0201_0-5]  76.53 55.47 180 bottom
C588  0.1uF  [CAP0201_0-5]  79.46 55.36 0 bottom
C589  0.1uF  [CAP0201_0-5]  74.46 55.35 180 bottom
C590  10uF  [CAP0402_0-75]  69.05 55.09 180 bottom
C591  0.1uF  [CAP0201_0-5]  71.54 54.88 180 bottom
C592  47uF  [CAP0805_1-5]  49.2 54.58 180 bottom
C593  47uF  [CAP0805_1-5]  44.54 54.58 0 bottom
C594  0.01uF  [CAP0201_0-5]  71.54 54.12 0 bottom
C595  10uF  [CAP0402_0-75]  80.62 53.79 270 bottom
C596  10uF  [CAP0402_0-75]  79.24 53.79 270 bottom
C597  0.1uF  [CAP0402_0-75]  59.44 52.96 180 bottom
C598  0.1uF  [CAP0402_0-75]  57.44 52.96 0 bottom
C599  0.1uF  [CAP0402_0-75]  28.54 48.77 270 bottom
C600  0.1uF  [CAP0402_0-75]  53.97 48.03 180 bottom
C601  0.1uF  [CAP0402_0-75]  51.97 48.03 0 bottom
C602  0.1uF  [CAP0201_0-5]  111.96 47.09 270 bottom
C603  0.1uF  [CAP0402_0-75]  48.61 46.95 180 bottom
C604  0.1uF  [CAP0402_0-75]  46.62 46.95 0 bottom
C605  1000pF  [CAP1206_1-75]  132.49 46.56 0 bottom
C606  0.1uF  [CAP0402_0-75]  28.48 46 270 bottom
C607  0.1uF  [CAP0402_0-75]  24.66 42.26 90 bottom
C608  0.1uF  [CAP0201_0-5]  28.33 41.96 270 bottom
C609  0.1uF  [CAP0201_0-5]  63.56 41.91 180 bottom
C610  1000pF  [CAP1206_1-75]  95.24 41.8 90 bottom
C611  1000pF  [CAP1206_1-75]  113.56 41.78 90 bottom
C612  0.1uF  [CAP0201_0-5]  28.33 40.44 90 bottom
C613  0.1uF  [CAP0201_0-5]  52.63 37.38 180 bottom
C614  22uF  [CAP0603_1]  92.49 34.96 180 bottom
C615  120pF  [CAP0201_0-5]  88.22 33.37 90 bottom
C616  0.1uF  [CAP0201_0-5]  92.91 33.35 180 bottom
C617  0.1uF  [CAP0201_0-5]  27.5 32.06 0 bottom
C618  0.1uF  [CAP0201_0-5]  29.03 31.84 180 bottom
C619  0.1uF  [CAP0201_0-5]  27.72 30.5 0 bottom
C620  4.7uF  [CAP0603_1]  93.2 29.85 0 bottom
C621  0.1uF  [CAP0201_0-5]  27.72 29.74 0 bottom
C622  0.1uF  [CAP0201_0-5]  61.59 28.5 0 bottom
C623  10uF  [CAP0805_1-5]  53.07 28.25 0 bottom
C624  47uF  [CAP1206_2]  27.72 28.01 180 bottom
C625  0.1uF  [CAP0402_0-75]  18.64 26.02 270 bottom
C626  0.22uF  [CAP0402_0-75]  16.35 24.85 90 bottom
C627  2.2uF  [CAP0402_0-75]  24.18 24.34 90 bottom
C628  0.12uF  [CAP0603_1]  15.09 22.64 180 bottom
C629  0.1uF  [CAP0402_0-75]  24.26 22.36 90 bottom
C630  22uF  [CAP0805_1-5]  53.09 21.76 0 bottom
C631  4.7uF  [CAP0402_0-75]  45.68 21.24 0 bottom
C632  330pF  [CAP0402_0-75]  14.26 19.78 180 bottom
C633  22uF  [CAP0805_1-5]  53.09 19.73 0 bottom
C634  33pF  [CAP0201_0-5]  17.76 18.67 0 bottom
C635  15000pF  [CAP0402_0-75]  14.26 18.51 180 bottom
C636  0.1uF  [CAP0402_0-75]  19.48 18.44 180 bottom
C637  0.1uF  [CAP0201_0-5]  66.5 17.82 270 bottom
C638  0.1uF  [CAP0201_0-5]  57.16 17.65 90 bottom
C639  0.1uF  [CAP0201_0-5]  50.88 16.56 270 bottom
C640  0.1uF  [CAP0201_0-5]  52.38 15.23 180 bottom
C641  0.01uF  [CAP0201_0-5]  37.48 14.42 270 bottom
C642  0.01uF  [CAP0201_0-5]  41.9 13.93 270 bottom
C643  4.7uF  [CAP0805_1-5]  35.93 13.93 270 bottom
C644  4.7uF  [CAP0805_1-5]  43.42 13.83 270 bottom
C645  150uF_10V  [CAPT7343D_3-25]  64.96 13.78 0 bottom
C646  10uF  [CAP0603_1]  54.74 11.87 270 bottom
C647  10uF  [CAP0603_1]  56.52 11.84 270 bottom
C648  1000pF  [CAP1206_1-75]  28.1 9.13 90 bottom
C649  0.01uF  [CAP0201_0-5]  47.16 8.72 180 bottom
C650  0.01uF  [CAP0201_0-5]  51.67 8.61 0 bottom
C651  1000pF  [CAP1206_1-75]  42.83 8.45 90 bottom
C652  0.01uF  [CAP0201_0-5]  47.15 7.56 180 bottom
C653  0.01uF  [CAP0201_0-5]  51.66 7.12 0 bottom
C654  0.01uF  [CAP0201_0-5]  36.17 4.59 0 bottom
C655  0.01uF  [CAP0201_0-5]  32.61 4.59 180 bottom
C656  1000pF  [CAP1206_1-75]  57.48 3.3 180 bottom
C657  1.0uF  [EMIFIL_NFM15CC_0402_0-5]  73.96 79.7 180 bottom
C658  1.0uF  [EMIFIL_NFM15CC_0402_0-5]  79.16 83.59 225 bottom
C659  1.0uF  [EMIFIL_NFM15CC_0402_0-5]  77.56 81.99 225 bottom
C660  1.0uF  [EMIFIL_NFM15CC_0402_0-5]  77.56 78.79 135 bottom
C661  1.0uF  [EMIFIL_NFM15CC_0402_0-5]  74.51 82.14 135 bottom
C662  1.0uF  [EMIFIL_NFM15CC_0402_0-5]  73.96 77.63 180 bottom
C663  1.0uF  [EMIFIL_NFM15CC_0402_0-5]  75.5 80.02 225 bottom
C664  10uF  [EMIFIL_NFM18C_0603_1-4]  75.18 67.14 0 top
C665  1.0uF  [EMIFIL_NFM15CC_0402_0-5]  75.72 76.53 45 bottom
C666  1.0uF  [EMIFIL_NFM15CC_0402_0-5]  74.21 75.25 180 bottom
C667  1.0uF  [EMIFIL_NFM15CC_0402_0-5]  74.36 76.39 135 bottom
C668  1.0uF  [EMIFIL_NFM15CC_0402_0-5]  77.56 76.39 225 bottom
C669  1.0uF  [EMIFIL_NFM15CC_0402_0-5]  67 71.43 135 bottom
C670  1.0uF  [EMIFIL_NFM15CC_0402_0-5]  83.96 71.59 225 bottom
D1  TPD1E10B06DPYR  [DIO_DFN0402_0-5]  124.03 63.09 0 top
D2  PLVA650A  [DIO_SOT23_123]  32.84 61.33 0 top
D3  TPD1E10B06DPYR  [DIO_DFN0402_0-5]  18.58 33.63 180 top
D4  BZX84C6V8LT1G  [SOT23-123_1-2]  70.18 20.77 90 top
D5  BAT54CWT1G  [DIO_SOT323-3_1-1]  33.58 19.48 90 top
D6  BZX84C6V8LT1G  [SOT23-123_1-2]  55.75 12.06 90 top
D7  TPD1E01B04DPLT  [DIO_DFN0201_0-4]  33.45 10.52 0 top
D8  TPD1E01B04DPLT  [DIO_DFN0201_0-4]  47.86 9.77 90 top
D9  ESD122DMXR  [X2SON3_ESD122DMX_30X40_0-4]  49.39 9.53 270 top
D10  TPD1E10B06DPYR  [DIO_DFN0402_0-5]  28.41 82.97 0 bottom
D11  TPD1E10B06DPYR  [DIO_DFN0402_0-5]  28.41 76.11 0 bottom
D12  TPD1E10B06DPYR  [DIO_DFN0402_0-5]  63.49 40.65 180 bottom
D13  TPD1E10B06DPYR  [DIO_DFN0402_0-5]  52.69 36.38 180 bottom
D14  TPD1E10B06DPYR  [DIO_DFN0402_0-5]  61.53 29.3 0 bottom
D15  XBS104S13R  [DIO_SOD323_1]  25.95 23.49 90 bottom
D16  TPD1E01B04DPLT  [DIO_DFN0201_0-4]  51.69 5.07 90 bottom
D17  TPD1E01B04DPLT  [DIO_DFN0201_0-4]  34.54 4.79 180 bottom
FL1  120E  [EMIFIL_BLM18P_0603_0-8]  113.53 170.22 0 top
FL2  120E  [EMIFIL_BLM18P_0603_0-8]  75.24 164.57 180 top
FL3  120E  [EMIFIL_BLM15A_0402_0-6]  34.95 164.42 0 top
FL4  120E  [EMIFIL_BLM15A_0402_0-6]  21.49 160.56 270 top
FL5  120E  [EMIFIL_BLM15A_0402_0-6]  43.26 156.18 90 top
FL6  120E  [EMIFIL_BLM15A_0402_0-6]  89.77 81.5 270 top
FL7  26E  [EMIFIL_BLM18K_0603]  90.04 79.38 180 top
FL8  26E  [EMIFIL_BLM18K_0603]  90.04 77.53 180 top
FL9  120E  [EMIFIL_BLM15A_0402_0-6]  59.82 72.26 90 top
FL10  120E  [EMIFIL_BLM15A_0402_0-6]  69.81 35.04 270 top
FL11  120E  [EMIFIL_BLM15A_0402_0-6]  64.76 116.27 270 bottom
FL12  120E  [EMIFIL_BLM15A_0402_0-6]  84.25 110.4 270 bottom
FL13  120E  [EMIFIL_BLM15A_0402_0-6]  89.75 79.51 180 bottom
FL14  26E  [EMIFIL_BLM18K_0603]  58.15 78.1 180 bottom
FL15  120E  [EMIFIL_BLM15A_0402_0-6]  56.18 74.96 0 bottom
FL16  120E  [EMIFIL_BLM15A_0402_0-6]  68.19 51.39 90 bottom
FL17  120E  [EMIFIL_BLM15A_0402_0-6]  29.75 45.97 90 bottom
FL18  120E  [EMIFIL_BLM15A_0402_0-6]  22.17 42.78 180 bottom
J1  CON_AUDIOJACK6_STX-4235  [CON_AV6_STX-4235-3-3_S_R_T_26]  65.48 184.46 180 top
J2  CON_AUDIOJACK6_STX-4235  [CON_AV6_STX-4235-3-3_S_R_T_26]  82.63 184.46 180 top
J3  CON_AUDIOJACK6_STX-4235  [CON_AV6_STX-4235-3-3_S_R_T_26]  99.77 184.46 180 top
J4  CON_AUDIOJACK6_STX-4235  [CON_AV6_STX-4235-3-3_S_R_T_26]  117.17 184.46 180 top
J5  CON_RCAJACK3_RCJ-022  [CON_RCAJACK3_RCJ-02X_S_S_T_16]  42.07 181.28 180 top
J6  CON_RCAJACK3_RCJ-022  [CON_RCAJACK3_RCJ-02X_S_S_T_16]  58.07 181.28 180 top
J7  HDR_1X2  [HDR_1X2_90120-0122_S_T_5-6]  80.35 168.64 0 top
J8  HDR_1X6  [HDR_1X6_61300611121_S_T_8-6]  111.03 146.24 270 top
J9  HDR_1X3  [HDR_1X3_100_S_T]  33.99 144.14 270 top
J10  HDR_1X2  [HDR_1X2_90120-0122_S_T_5-6]  95.22 137.52 270 top
J11  HDR_1X6  [HDR_1X6_61300611121_S_T_8-6]  39.65 128.12 90 top
J12  RECP_40X2  [CON_40X2_QSE-040-01_S_S_S]  20.15 118.76 90 top
J13  RECP_40X2  [CON_40X2_QSE-040-01_S_S_S]  126.85 118.75 270 top
J14  HDR_2X10  [HDR_2X10_FTR-110-51-D-06_S_S_8-7]  110.8 98.77 180 top
J15  HDR_1X3  [HDR_1X3_100_S_T]  29.96 89.86 270 top
J16  HDR_1X2  [HDR_1X2_61300211121_S_T_8-6]  29.27 58.34 90 top
J17  CON_MUSB-B_5_F  [CON_MUSBB5_629105150521_S_R_S_2-7]  134.3 52.29 90 top
J18  CON_BTOB_2X24_M  [CON_BTOB2X24_DF40GB-48DP_P_S_S_1-3]  87.81 40.98 0 top
J19  CON_BTOB_2X24_M  [CON_BTOB2X24_DF40GB-48DP_P_S_S_1-3]  120.24 40.98 0 top
J20  HDR_1X2  [HDR_1X2_61300211121_S_T_8-6]  58.32 40.65 90 top
J21  HDR_2X5  [HDR_2X5_PEC05DAAN_S_T_8-6]  45.22 33.2 90 top
J22  CON_MUSB-B_5_F  [CON_MUSBB5_629105150521_S_R_S_2-7]  12.7 31.11 270 top
J23  CON_USB-A_4_F  [CON_USBA4_629104151_S_R_S_7-4]  65.04 6.99 0 top
J24  CON_USB-C_24_F  [CON_USBC24_2012670_S_R_S_3-9]  34.39 3.88 0 top
J25  CON_USB-C_24_F  [CON_USBC24_2012670_S_R_S_3-9]  49.39 3.88 0 top
J26  CON_SDCARD9_MEM2052-00-195-00-A  [CON_SD9_MEM2052-00-195-00_S_R_S_2]  18.57 156.96 90 bottom
L1  47uH  [INDP1210]  26.7 173.79 90 top
L2  2.2uH  [IND0806]  70.08 164.82 180 top
L3  2.2uH  [IND0806]  80.86 154.92 0 top
L4  0.22uH  [IND1210_1-2]  44.96 68.99 90 top
L5  0.22uH  [IND1210_1-2]  48.78 68.99 90 top
L6  0.22uH  [IND1210_1-2]  44.96 55.55 270 top
L7  0.22uH  [IND1210_1-2]  48.78 55.55 270 top
L8  1.5uH  [IND_XFL4020_170X170_SMD_2-1]  55.02 23.96 270 top
L9  90E  [IND4_DLW21H_90X60_SMD_1-4]  65.08 20.11 270 top
L10  90E  [IND4_DLW21H_90X60_SMD_1-4]  49.39 12.17 270 top
L11  0.47uH  [IND0806_1-2]  94.61 32.43 90 bottom
L12  1.8uH  [IND_XAL7070_300X310_SMD_7]  27.33 17.13 0 bottom
LD1  150080VS75000  [LED_150080VS75000_80X50_SMD_0-8]  118.65 94.58 90 top
LD2  150080VS75000  [LED_150080VS75000_80X50_SMD_0-8]  23.15 75.22 0 top
LD3  150040RS73220  [LED_150040GS73220_40X20_SMD_0-4]  135.3 68.9 90 top
LD4  150040VS73220  [LED_150040GS73220_40X20_SMD_0-4]  35.73 66.42 0 top
LD5  150080VS75000  [LED_150080VS75000_80X50_SMD_0-8]  130.19 66.32 0 top
LD6  150080VS75000  [LED_150080VS75000_80X50_SMD_0-8]  37.15 86.97 180 top
LD7  150080VS75000  [LED_150080VS75000_80X50_SMD_0-8]  31.95 52.26 0 top
LD8  150080VS75000  [LED_150080VS75000_80X50_SMD_0-8]  33.38 14.44 90 top
LD9  150080VS75000  [LED_150080VS75000_80X50_SMD_0-8]  47.07 12.94 270 top
LD10  150080VS75000  [LED_150080VS75000_80X50_SMD_0-8]  48.23 126.66 180 top
MOD1  PLR237/T10BK  [MOD5_PLR135T10_10-3]  24.66 179.71 0 top
NOREF  -  [unnamed]  138 5.08 90 top
NOREF#2  -  [unnamed#2]  76.74 40.35 270 top
NOREF#3  -  [unnamed]  9 182.88 270 top
NOREF#4  -  [unnamed#2]  133.17 3.9 270 top
NOREF#5  -  [unnamed#2]  133.19 184.15 270 top
NOREF#6  -  [unnamed]  9 69.27 270 top
NOREF#7  -  [#3]  10 0 90 top
NOREF#8  -  [unnamed#2]  133.3 40.35 270 top
NOREF#9  -  [unnamed]  9 5.08 270 top
NOREF#10  -  [unnamed#2]  142.94 4 270 top
NOREF#11  -  [unnamed]  9 133.46 270 top
NOREF#12  -  [unnamed#2]  126.84 91.76 0 top
NOREF#13  -  [unnamed#2]  143 183.9 0 top
NOREF#14  -  [#3]  0 187.96 0 top
NOREF#15  -  [unnamed#2]  100.74 3.9 270 top
NOREF#16  -  [unnamed#2]  142.94 9.33 180 top
NOREF#17  -  [unnamed#2]  109.17 40.35 270 top
NOREF#18  -  [unnamed#2]  3.94 9.33 180 top
NOREF#19  -  [#3]  10 187.96 0 top
NOREF#20  -  [#3]  28.5 -83.7 0 top
NOREF#21  -  [unnamed#2]  20.16 145.75 180 top
NOREF#22  -  [unnamed#2]  13.81 3.81 90 top
NOREF#23  -  [unnamed#2]  143 178.56 0 top
NOREF#24  -  [unnamed#2]  13.69 8.75 0 top
NOREF#25  -  [unnamed#2]  100.87 40.35 270 top
NOREF#26  -  [unnamed#2]  126.84 145.75 180 top
NOREF#27  -  [unnamed]  138 133.46 90 top
NOREF#28  -  [unnamed#2]  133.39 175.34 0 top
NOREF#29  -  [unnamed#2]  4 183.9 0 top
NOREF#30  -  [unnamed#2]  13.69 175.34 0 top
NOREF#31  -  [unnamed]  138 182.88 90 top
NOREF#32  -  [#3]  39.04 11.04 0 top
NOREF#33  -  [unnamed#2]  4 178.56 0 top
NOREF#34  -  [unnamed#2]  13.81 184.15 90 top
NOREF#35  -  [unnamed#2]  3.94 4 270 top
NOREF#36  -  [unnamed]  138 69.27 90 top
NOREF#37  -  [unnamed#2]  20.16 91.76 0 top
NOREF#38  -  [#3]  -299.12 -71.04 0 top
NOREF#39  -  [unnamed#2]  4 178.56 180 bottom
NOREF#40  -  [unnamed#2]  3.94 9.33 180 bottom
NOREF#41  -  [unnamed#2]  133.39 175.34 180 bottom
NOREF#42  -  [unnamed#2]  143 178.56 180 bottom
NOREF#43  -  [unnamed#2]  142.94 9.33 180 bottom
NOREF#44  -  [unnamed#2]  13.69 8.75 180 bottom
NOREF#45  -  [unnamed#2]  13.69 175.34 180 bottom
Q1  CSD16301Q2  [WSON6_CSD13202Q2_80X80_0-8]  121.33 94.51 90 top
Q2  ABC817-40-HF  [SOT23-123_1-2]  23.23 72.22 180 top
Q3  BSS138LT1G  [SOT23-123_1-2]  36.38 68.96 180 top
Q4  BSS138LT1G  [SOT23-123_1-2]  32.02 65.01 0 top
Q5  CSD16301Q2  [WSON6_CSD13202Q2_80X80_0-8]  52.43 126.83 180 bottom
Q6  IRLML6401  [TO_SOT23-123]  31.75 84.23 90 bottom
Q7  IRLML6401  [TO_SOT23-123]  31.75 77.32 90 bottom
Q8  CSD25310Q2  [SON6_CSD17313Q2_80X80]  55.37 17.12 0 bottom
Q9  CSD25310Q2  [SON6_CSD17313Q2_80X80]  52.67 17.12 180 bottom
Q10  CSD16301Q2  [WSON6_CSD13202Q2_80X80_0-8]  47.63 16.26 0 bottom
Q11  CSD17575Q3  [VSON8_CSD173_130X130_1-1]  24.53 10.33 90 bottom
R1  75E_1%  [RES0402_0-5]  36.44 174.9 180 top
R2  75E_1%  [RES0402_0-5]  53.39 174.9 0 top
R3  4.3K  [RES0402_0-5]  67.56 174.35 270 top
R4  4.3K  [RES0402_0-5]  68.83 174.35 270 top
R5  4.3K  [RES0402_0-5]  71.4 174.35 270 top
R6  4.3K  [RES0402_0-5]  72.67 174.35 270 top
R7  4.3K  [RES0402_0-5]  84.71 174.35 270 top
R8  4.3K  [RES0402_0-5]  85.98 174.35 270 top
R9  4.3K  [RES0402_0-5]  88.55 174.35 270 top
R10  4.3K  [RES0402_0-5]  89.82 174.35 270 top
R11  0E  [RES0201_0-5]  41.92 172.35 90 top
R12  10K  [RES0201_0-5]  20.81 172.27 0 top
R13  0E  [RES0201_0-5]  46.33 172.21 90 top
R14  0E  [RES0201_0-5]  48.29 172.18 90 top
R15  0E  [RES0201_0-5]  47.31 172.18 90 top
R16  0E  [RES0201_0-5]  43.02 171.87 90 top
R17  10K  [RES0201_0-5]  17.11 167.44 90 top
R18  10K  [RES0201_0-5]  14.67 165.9 90 top
R19  0E  [RES0201_0-5]  17.97 165.67 90 top
R20  10K  [RES0201_0-5]  77.9 164.8 270 top
R21  0E  [RES0201_0-5]  15.6 164.63 0 top
R22  10K  [RES0201_0-5]  79.14 164.5 90 top
R23  10K  [RES0201_0-5]  80.03 164.5 270 top
R24  0E  [RES0201_0-5]  97.02 163.78 180 top
R25  0E  [RES0201_0-5]  114.42 163.78 180 top
R26  10K  [RES0201_0-5]  77.12 163.68 180 top
R27  10K  [RES0201_0-5]  123.23 161.84 180 top
R28  4.7K  [RES0201_0-5]  124.93 161.78 0 top
R29  10K  [RES0201_0-5]  104.41 161.49 180 top
R30  10K  [RES0201_0-5]  121.83 161.17 90 top
R31  10K  [RES0201_0-5]  103.1 160.95 0 top
R32  10K  [RES0201_0-5]  120.5 160.95 0 top
R33  10K  [RES0201_0-5]  106.42 160.89 0 top
R34  0E  [RES0201_0-5]  76.72 160.77 0 top
R35  22K  [RES0402_0-5]  123.18 160.62 0 top
R36  4.7K  [RES0201_0-5]  107.63 160.58 90 top
R37  0E  [RES0201_0-5]  104.13 160.32 90 top
R38  0E  [RES0201_0-5]  76.72 159.86 0 top
R39  22E  [RES0201_0-5]  39.75 159.27 90 top
R40  0E  [RES0201_0-5]  45.17 159.11 270 top
R41  0E  [RES0201_0-5]  46.01 159.11 270 top
R42  0E  [RES0201_0-5]  47.2 159.11 270 top
R43  0E  [RES0201_0-5]  48.12 159.11 270 top
R44  0E  [RES0201_0-5]  49.03 159.11 270 top
R45  0E  [RES0201_0-5]  49.95 159.11 270 top
R46  0E  [RES0201_0-5]  74.23 158.97 180 top
R47  10K  [RES0201_0-5]  48.73 157.38 90 top
R48  10K  [RES0201_0-5]  49.64 157.38 270 top
R49  10K  [RES0201_0-5]  44.87 157.38 270 top
R50  10K  [RES0201_0-5]  45.78 157.38 90 top
R51  0E  [RES0201_0-5]  46.8 157.38 270 top
R52  0E  [RES0201_0-5]  47.71 157.38 270 top
R53  10K  [RES0201_0-5]  36.84 156.69 90 top
R54  10K  [RES0201_0-5]  17.72 156.58 180 top
R55  10K  [RES0201_0-5]  22.22 156.08 0 top
R56  4.7K  [RES0201_0-5]  131.53 155.8 180 top
R57  10K  [RES0201_0-5]  17.72 155.64 180 top
R58  4.7K  [RES0201_0-5]  125.83 155.42 0 top
R59  10K  [RES0402_0-5]  53.19 155.28 180 top
R60  10K  [RES0201_0-5]  70.91 155.23 90 top
R61  10K  [RES0201_0-5]  71.8 155.23 270 top
R62  10K  [RES0201_0-5]  72.69 155.23 90 top
R63  10K  [RES0201_0-5]  73.58 155.23 270 top
R64  10K  [RES0201_0-5]  22.21 155.13 0 top
R65  10K  [RES0201_0-5]  17.72 154.7 180 top
R66  10K  [RES0201_0-5]  22.22 154.2 0 top
R67  0E  [RES0603_0-75]  87.87 153.44 180 top
R68  10K  [RES0402_0-5]  92.1 153.34 270 top
R69  10K  [RES0402_0-5]  132.09 153.14 180 top
R70  10K  [RES0201_0-5]  26.02 153.12 270 top
R71  1K  [RES0402_0-5]  16.66 152.43 90 top
R72  10K  [RES0402_0-5]  50.01 151.98 90 top
R73  0E  [RES0201_0-5]  119.19 151.23 90 top
R74  0E  [RES0201_0-5]  118.22 151.22 90 top
R75  4.7K  [RES0201_0-5]  116.46 151.21 270 top
R76  4.7K  [RES0201_0-5]  117.23 151.21 90 top
R77  0E  [RES0805_0-75]  15.77 150.52 0 top
R78  10K  [RES0402_0-5]  89.44 150.28 270 top
R79  0E  [RES0201_0-5]  51.71 150.13 90 top
R80  0E  [RES0603_0-75]  74.93 150.09 90 top
R81  33E  [RES0402_0-5]  47.73 149.25 90 top
R82  0E  [RES0402_0-5]  49 149.25 270 top
